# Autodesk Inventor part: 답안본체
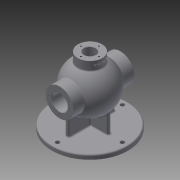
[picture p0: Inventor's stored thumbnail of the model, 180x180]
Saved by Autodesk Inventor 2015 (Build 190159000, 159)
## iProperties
Created: 2020-08
Part Number: 답안본체
Material: 일반
Document SubType Name: Modeling
Designer: now
Density: 1 g/cm^3
Appearance: 기본값
Mass: 649.13 g
Surface Area: 1342.09 cm^2
Volume: 649.13 cm^3
Author: now
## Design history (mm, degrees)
sketch "스케치1"
  geometry: C1 r 85 at (0, 0); 1 further point
  constraints: 1 centre point, 1 coincident
  dimensions: "d0" = 170 diameter of C1
extrude "돌출1" new body sketch "스케치1" distance "d1" = 10; taper "d2" = 0 deg
fillet "모깎기1" dims "d3" = 3
sketch "스케치2"
  geometry: L1 (-43, -4)-(43, -4); L2 (43, -4)-(43, 4); L3 (43, 4)-(-43, 4); L4 (-43, 4)-(-43, -4); L5 (-43, -4)-(43, 4); L6 (43, -4)-(-43, 4); L7 (-4, -52)-(4, -52); L8 (4, -52)-(4, 52); L9 (4, 52)-(-4, 52); L10 (-4, 52)-(-4, -52); L11 (-4, -52)-(4, 52); L12 (4, -52)-(-4, 52); C1 r 82 at (0, 0) reference
  constraints: 24 end point, 4 midpoint, 4 parallel, 2 horizontal, 2 perpendicular
  dimensions: "d42" = 8 distance between parallel lines of L8 L10; "d43" = 8 distance between parallel lines of L3 L1; "d44" = 86 distance of L1.start L1.end; "d45" = 104 distance of L7.end L8.end
extrude "돌출2" join sketch "스케치2" distance "d8" = 75; taper "d9" = 0 deg
node "작업 평면1"
fillet "모깎기2" dims "d46" = 3
sketch "스케치7"
  geometry: L1 (-82, 10)-(-52, 10) reference; L2 (-52, 10)-(-52, 85) reference; L3 (-52, 85)-(52, 85) reference; L4 (52, 85)-(52, 10) reference; L5 (52, 10)-(82, 10) reference; L6 (85, 7)-(85, 0) reference; L7 (85, 0)-(-85, 0) reference; L8 (-85, 0)-(-85, 7) reference; L9 (-53, 85)-(53, 85); L10 (4, 85)-(4, 10) reference; A1 r 3 centre (-82, 7) between (-82, 10) and (-85, 7) reference; A2 r 3 centre (82, 7) between (85, 7) and (82, 10) reference; A3 r 53 centre (0, 85) between (53, 85) and (-53, 85); 2 further points
  constraints: 2 end point, 2 midpoint, 2 point on circle, 1 centre point, 1 coincident, 1 horizontal
  dimensions: "d49" = 53 radius of A3
revolve "회전3" sketch "스케치7" stored, may be unused: angle "d50" = 90 deg
sketch "스케치4"
  geometry: C1 r 27 at (0, 0); 1 further point
  constraints: 1 centre point, 1 coincident
  dimensions: "d14" = 54 diameter of C1
extrude "돌출3" join sketch "스케치4" stored distance "d15" = 65; taper "d16" = 0 deg
sketch "스케치5"
  geometry: L1 (-82, 10)-(-43, 10) reference; L2 (-27, 130.607)-(-27, 150) reference; L3 (-27, 150)-(27, 150) reference; L4 (27, 150)-(27, 130.607) reference; L5 (43, 10)-(82, 10) reference; L6 (85, 7)-(85, 0) reference; L7 (85, 0)-(-85, 0) reference; L8 (-85, 0)-(-85, 7) reference; L9 (-43, 10)-(-43, 54.016) reference; L10 (43, 54.016)-(43, 10) reference; C1 r 31 at (0, 85); A1 r 3 centre (-82, 7) between (-82, 10) and (-85, 7) reference; A2 r 3 centre (82, 7) between (85, 7) and (82, 10) reference; A3 r 53 centre (0, 85) between (-27, 130.607) and (-53, 85) reference; A4 r 53 centre (0, 85) between (-53, 85) and (-43, 54.016) reference; A5 r 53 centre (0, 85) between (43, 54.016) and (53, 85) reference; A6 r 53 centre (0, 85) between (53, 85) and (27, 130.607) reference; 2 further points
  constraints: 1 centre point, 1 coincident
  dimensions: "d17" = 62 diameter of C1
extrude "돌출4" join sketch "스케치5" stored distance "d18" = 136; taper "d19" = 0 deg
sketch "스케치6"
  geometry: L1 (-82, 10)-(-52, 10) reference; L2 (-52, 54)-(-68, 54) reference; L3 (-68, 54)-(-68, 116) reference; L4 (-68, 116)-(-42.988, 116) reference; L5 (-27, 130.607)-(-27, 150) reference; L6 (-27, 150)-(27, 150) reference; L7 (27, 150)-(27, 130.607) reference; L8 (42.988, 116)-(68, 116) reference; L9 (68, 116)-(68, 54) reference; L10 (68, 54)-(52, 54) reference; L11 (52, 10)-(82, 10) reference; L12 (85, 7)-(85, 0) reference; L13 (85, 0)-(-85, 0) reference; L14 (-85, 0)-(-85, 7) reference; L15 (-43, 85)-(43, 85); L16 (-52, 10)-(-52, 54) reference; L17 (52, 54)-(52, 10) reference; A1 r 3 centre (-82, 7) between (-82, 10) and (-85, 7) reference; A2 r 3 centre (82, 7) between (85, 7) and (82, 10) reference; A3 r 43 centre (0, 85) between (43, 85) and (-43, 85); A4 r 53 centre (0, 85) between (-27, 130.607) and (-42.988, 116) reference; A5 r 53 centre (0, 85) between (42.988, 116) and (27, 130.607) reference; 4 further points
  constraints: 2 coincident, 2 end point, 2 point on circle, 1 centre point, 1 horizontal, 1 midpoint
  dimensions: "d20" = 86 diameter of A3
revolve "회전2" sketch "스케치6" stored, may be unused: angle "d21" = 90 deg
hole "구멍1" diameter "d24" = 35; stored, may be unused: countersink angle "d28" = 90 deg, drill point angle "d30" = 118 deg; dims "d22" = 10, "d23" = 10, "d25" = 6, "d26" = 4, "d27" = 2, "d29" = 8
hole "구멍2" diameter "d33" = 26; stored, may be unused: countersink angle "d37" = 90 deg, drill point angle "d39" = 118 deg; dims "d34" = 6, "d35" = 4, "d36" = 2, "d38" = 8, "d40" = 10, "d41" = 10
sketch "스케치8"
  geometry: C1 r 17.5 at (0, 0) reference; 2 further points
  constraints: 1 vertical alignment
  dimensions: "d51" = 24 distance of C1.centre point (0, 24)
hole "구멍3" sketch "스케치8" at (0, 24) diameter "d52" = 3.242; stored, may be unused: countersink angle "d56" = 90 deg, drill point angle "d58" = 118 deg; dims "d53" = 12, "d54" = 4, "d55" = 2, "d57" = 15
sketch "스케치9"
  geometry: C1 r 13 at (0, 0) reference; 1 further point
  constraints: 1 horizontal alignment
  dimensions: "d62" = 20 distance of C1.centre point (20, 0)
hole "구멍4" sketch "스케치9" at (20, 0) diameter "d63" = 3.242; stored, may be unused: countersink angle "d67" = 90 deg, drill point angle "d69" = 118 deg; dims "d64" = 12, "d65" = 4, "d66" = 2, "d68" = 15
fillet "모깎기3" dims "d73" = 3
chamfer "모따기1" distance "d74" = 1; stored, may be unused: second distance "d75" = 2, angle "d76" = 45 deg
sketch "스케치10"
  geometry: C1 r 82 at (0, 0) reference; 1 further point
  constraints: 1 horizontal alignment
  dimensions: "d77" = 72.5 distance of point (-72.5, 0) C1.centre
hole "구멍5" sketch "스케치10" at (-72.5, 0) diameter "d78" = 9; stored, may be unused: countersink angle "d82" = 90 deg, drill point angle "d84" = 118 deg; dims "d79" = 12, "d80" = 4, "d81" = 2, "d83" = 15
fillet "모깎기4" dims "d88" = 3
node "작업 평면2"
sketch "스케치11"
  geometry: L1 (27, 150)-(-27, 150) reference; L2 (-27, 132.286)-(27, 132.286) reference; 2 further points
  constraints: 1 other
  dimensions: "d90" = 9 distance from line of L1 point (0, 141); "d91" = 27 horizontal distance of L1.end point (0, 141)
feature "엠보싱1" sketch "스케치11" dims "d2" = 0, "d92" = 0.5, "d93" = 0
node "작업 평면3"
sketch "스케치12"
  geometry: C1 r 17.5 at (0, 0) reference; C2 r 18.5 at (0, 0); 1 further point
  constraints: 1 centre point, 1 coincident
  dimensions: "d95" = 37 diameter of C2
extrude "돌출5" cut sketch "스케치12" distance "d96" = 1.75; taper "d97" = 0 deg
node "솔리드1"
pattern_circular "원형 패턴1" dims angle "d60" = 360 deg
mirror "대칭1"
pattern_circular "원형 패턴2" dims angle "d71" = 360 deg
pattern_circular "원형 패턴3" dims angle "d86" = 360 deg
node "투영된 루프1"
node "절단 모서리 투영2"
node "절단 모서리 투영3"
node "절단 모서리 투영4"
other parameters: "d10" = 106, "d48" = 106, "d89" = 27, "d94" = -16
